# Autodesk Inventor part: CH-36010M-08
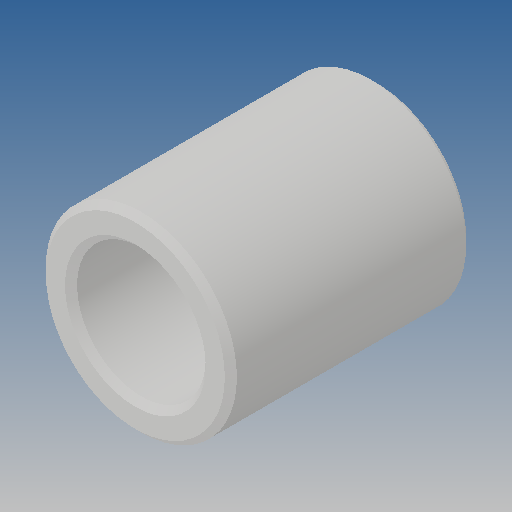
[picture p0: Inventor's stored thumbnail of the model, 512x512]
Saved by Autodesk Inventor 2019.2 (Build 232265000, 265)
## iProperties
Created: 2012-09
Part Number: CH-36010M-08
Material: Ogólny
Document SubType Name: Modeling
Designer: CADENGINEERING4
Density: 1 g/cm^3
Appearance: Domyślna
Author: CADENGINEERING4
Revision Number: ÈÎºÎ
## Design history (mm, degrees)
feature "µ¹½Ç1"
node "Bryła1"
